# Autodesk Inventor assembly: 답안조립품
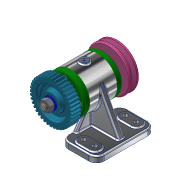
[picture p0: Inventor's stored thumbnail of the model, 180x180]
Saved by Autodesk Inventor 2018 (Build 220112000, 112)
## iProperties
Created: 2023-08
Part Number: 답안조립품
Material: 일반
Document SubType Name: Assembly
Designer: home
Author: home
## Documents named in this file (12)
- C:\Users\home\Desktop\730806V1011\답안조립품.iam
- C:\Users\home\Desktop\730806V1011\본체.ipt
- C:\Users\home\Desktop\730806V1011\V벨트풀리.ipt
- C:\Users\home\Desktop\730806V1011\너트 M12x1.25.ipt
- C:\Users\home\Desktop\730806V1011\베어링 6204.ipt
- C:\Users\home\Desktop\730806V1011\볼트 M4 x 12.ipt
- C:\Users\home\Desktop\730806V1011\스퍼기어.ipt
- C:\Users\home\Desktop\730806V1011\오일실 20x35x8.ipt
- C:\Users\home\Desktop\730806V1011\와셔 12x24.ipt
- C:\Users\home\Desktop\730806V1011\축.ipt
- C:\Users\home\Desktop\730806V1011\커버.ipt
- C:\Users\home\Desktop\730806V1011\키 5x5.ipt
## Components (1 placed, 1 different names)
1. V벨트풀리:1
